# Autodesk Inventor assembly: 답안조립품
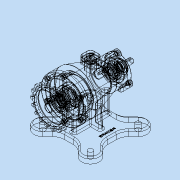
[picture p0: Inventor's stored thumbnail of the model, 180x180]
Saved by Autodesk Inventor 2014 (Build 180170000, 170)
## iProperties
Created: 2018-03
Part Number: 답안조립품
Document SubType Name: Assembly
Designer: kb542
Author: kb542
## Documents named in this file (15)
- C:\Users\kb542\Desktop\480307V1027\답안조립품.iam
- C:\Users\kb542\Desktop\480307V1027\본체.ipt
- C:\Users\kb542\Desktop\480307V1027\뒤커버.ipt
- C:\Users\kb542\Desktop\480307V1027\마개.ipt
- C:\Users\kb542\Desktop\480307V1027\베어링-6200.ipt
- C:\Users\kb542\Desktop\480307V1027\베어링-6203.ipt
- C:\Users\kb542\Desktop\480307V1027\볼트 M4 x 12.ipt
- 볼트 M4 x 12.ipt
- C:\Users\kb542\Desktop\480307V1027\스프로킷.ipt
- C:\Users\kb542\Desktop\480307V1027\앞커버.ipt
- C:\Users\kb542\Desktop\480307V1027\오일 실 10 20 7.ipt
- C:\Users\kb542\Desktop\480307V1027\오일 실 17 30 8.ipt
- C:\Users\kb542\Desktop\480307V1027\축.ipt
- C:\Users\kb542\Desktop\480307V1027\키 5 x 5.ipt
- 키 5 x 5.ipt
